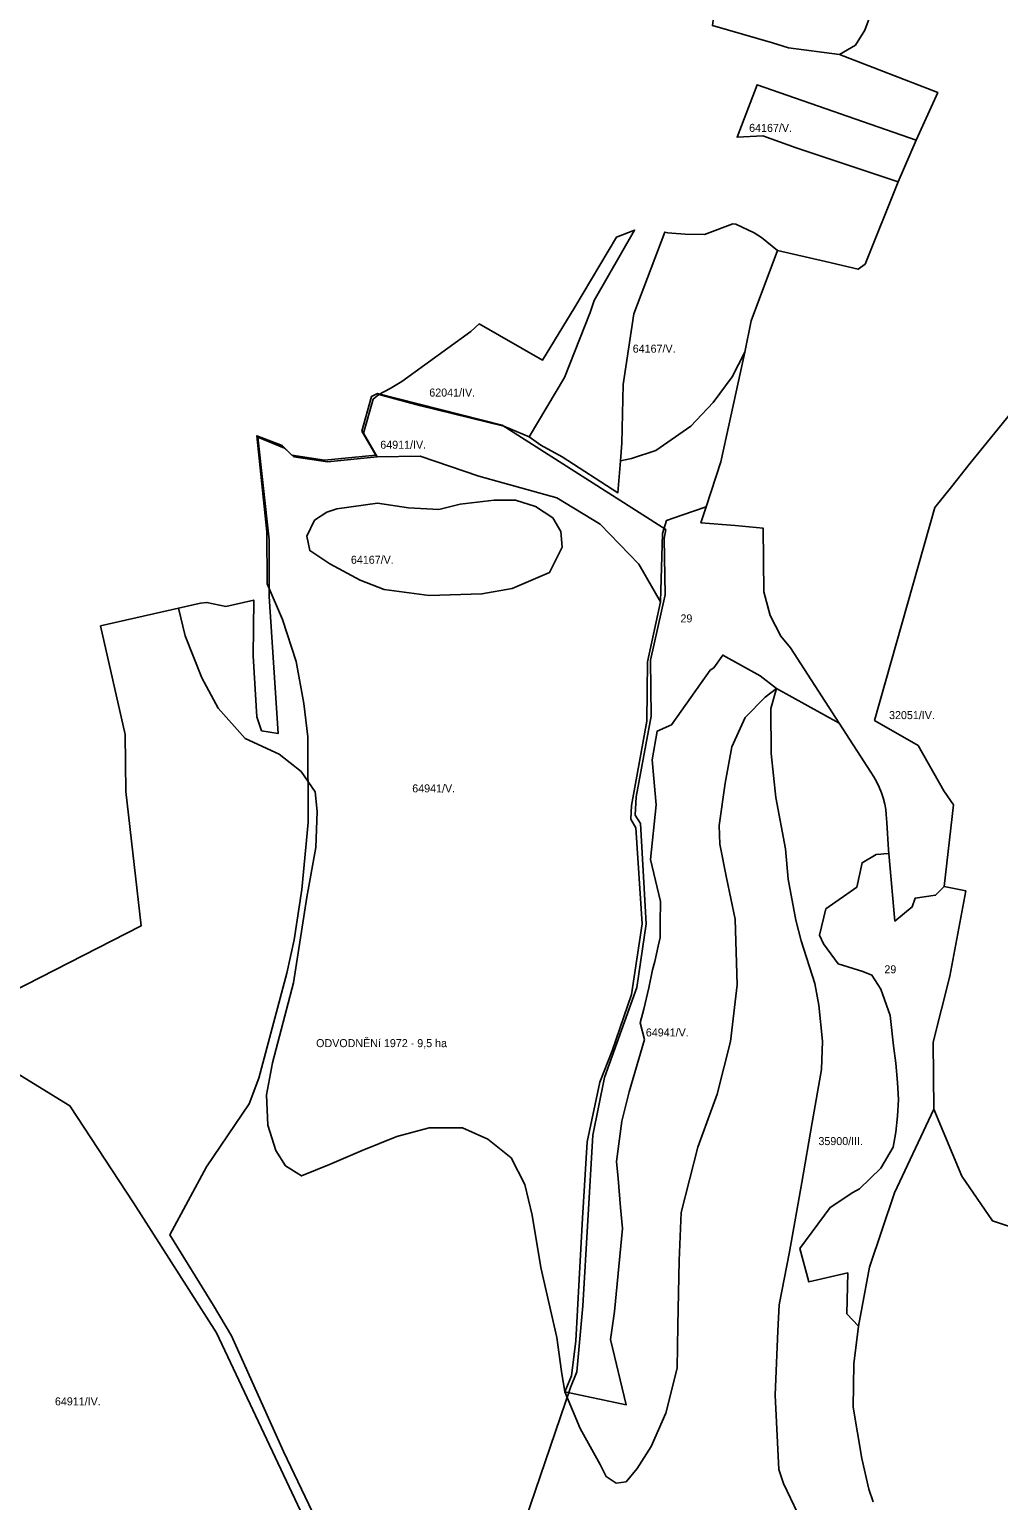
# Model space of a CAD drawing. Extents: x -521621 to -516761, y -1190184 to -1184927.
# Drawn here: x -519274 to -518790, y -1186738 to -1186003 of the extents above; entities that cross this region are included whole.
import ezdxf

# ---------------------------------------------------------------- set-up
doc = ezdxf.new("R2010")
doc.units = 0
doc.layers.add('BPEJ_s', color=7, linetype='Continuous')
doc.layers.add('odvodneni_s', color=7, linetype='Continuous')

msp = doc.modelspace()

# ---------------------------------------------------------------- linework, layer by layer
at = {"layer": 'BPEJ_s'}
for points in [[(-518927.24, -1185953.94), (-518919.2, -1185957.47), (-518903.58, -1185964.54), (-518887.75, -1185971.74), (-518858.33, -1185984.63), (-518853.23, -1185985.04), (-518849.62, -1185983.57), (-518850.9, -1185988.03), (-518856.42, -1186002.95), (-518861.03, -1186010.39), (-518869.09, -1186015.13), (-518894.47, -1186011.75), (-518902.58, -1186009.28), (-518932.52, -1186000.68), (-518929.68, -1185977.74), (-518926.98, -1185957.49)], [(-518839.76, -1186078.8), (-518890.62, -1186061.79), (-518907.36, -1186055.72), (-518920.21, -1186056.45), (-518910.27, -1186030.23), (-518830.77, -1186057.92)], [(-518978.56, -1186218.19), (-518977.87, -1186209.43), (-518977.14, -1186180.08), (-518971.74, -1186144.66), (-518956.26, -1186103.89), (-518954.89, -1186104.16), (-518952.82, -1186104.31), (-518946.24, -1186104.81), (-518936.52, -1186105.07), (-518922.31, -1186099.75), (-518920.92, -1186099.86), (-518911.74, -1186104.17), (-518907.96, -1186106.55), (-518900, -1186113.07), (-518913.14, -1186148.14), (-518916.35, -1186163.9), (-518922.7, -1186176.15), (-518932.15, -1186189.09), (-518943.34, -1186200.87), (-518960.9, -1186213.03), (-518973.06, -1186217.09)], [(-519099.23, -1186185.06), (-519093.67, -1186182.05), (-519087.79, -1186178.57), (-519053.23, -1186153.53), (-519049.1, -1186149.76), (-519017.53, -1186167.93), (-519001.26, -1186141.37), (-518980.5, -1186106.34), (-518971.45, -1186102.82), (-518991.71, -1186138.02), (-518993.72, -1186144.06), (-519006.47, -1186176.56), (-519024.12, -1186206.22), (-519036.73, -1186200.92), (-519078.87, -1186190.51)], [(-519100.11, -1186216.23), (-519106.93, -1186204.32), (-519102.12, -1186187.28), (-519099.23, -1186185.06), (-519078.87, -1186190.51), (-519036.73, -1186200.92), (-519024.12, -1186206.22), (-519018.33, -1186210.38), (-519007.58, -1186216.1), (-518979.81, -1186234.14), (-518978.56, -1186218.19), (-518973.06, -1186217.09), (-518960.9, -1186213.03), (-518943.34, -1186200.87), (-518932.15, -1186189.09), (-518922.7, -1186176.15), (-518916.35, -1186163.9), (-518924.26, -1186199.68), (-518928.29, -1186218.68), (-518935.71, -1186241.21), (-518947.84, -1186245.34), (-518955.44, -1186247.99), (-518957.48, -1186254.45), (-518958.55, -1186288.61), (-518969.39, -1186269.9), (-518988.69, -1186249.81), (-519010.3, -1186236.69), (-519049.28, -1186225.87), (-519078.61, -1186215.83)], [(-519199.32, -1186291.85), (-519188.43, -1186289.39), (-519185.21, -1186288.91), (-519175.79, -1186290.98), (-519161.77, -1186287.76), (-519162, -1186315.6), (-519160.16, -1186346.2), (-519157.86, -1186353.1), (-519149.59, -1186354.48), (-519154.05, -1186286.04), (-519154.05, -1186257.68), (-519159.74, -1186206.3), (-519146.35, -1186211.89), (-519141.76, -1186216.11), (-519124.9, -1186218.71), (-519100.11, -1186216.23), (-519078.61, -1186215.83), (-519049.28, -1186225.87), (-519010.3, -1186236.69), (-518988.69, -1186249.81), (-518969.39, -1186269.9), (-518958.55, -1186288.61), (-518964.97, -1186318.69), (-518965.37, -1186348.37), (-518972.98, -1186390.49), (-518973.26, -1186397.21), (-518970.84, -1186401.56), (-518967.71, -1186449.61), (-518973.02, -1186484.86), (-518982.62, -1186513.12), (-518988.81, -1186528.68), (-518995.15, -1186558.48), (-518997.41, -1186596.66), (-519000.81, -1186658.07), (-519003.05, -1186675.54), (-519006.29, -1186683.46), (-519007.95, -1186673.29), (-519010.28, -1186656.33), (-519018.25, -1186621.43), (-519022.57, -1186595.17), (-519026.22, -1186579.87), (-519033.2, -1186566.58), (-519044.83, -1186557.27), (-519057.45, -1186551.62), (-519074.06, -1186551.62), (-519090.34, -1186555.94), (-519107.62, -1186562.92), (-519123.9, -1186569.9), (-519137.85, -1186575.55), (-519145.83, -1186570.56), (-519150.81, -1186562.92), (-519154.8, -1186550.29), (-519155.46, -1186535), (-519152.47, -1186519.04), (-519141.84, -1186479.15), (-519135.19, -1186436.26), (-519130.72, -1186411.48), (-519130.11, -1186393.52), (-519131.03, -1186383.61), (-519138.15, -1186373.39), (-519148.98, -1186364.72), (-519166.01, -1186356.97), (-519179.62, -1186341.8), (-519187.67, -1186326.62), (-519196.03, -1186305.57)], [(-519030.98, -1186237.83), (-519020.92, -1186241.04), (-519012.32, -1186246.73), (-519008.38, -1186253.44), (-519007.66, -1186261.32), (-519013.93, -1186274.01), (-519032.59, -1186282.04), (-519047.75, -1186284.66), (-519074.14, -1186285.54), (-519096.6, -1186282.47), (-519108.56, -1186277.8), (-519123.72, -1186269.63), (-519133.78, -1186263.07), (-519135.24, -1186255.77), (-519131.45, -1186247.9), (-519125.32, -1186243.81), (-519120.3, -1186242.09), (-519099.84, -1186239.39), (-519084.4, -1186241.71), (-519069.35, -1186242.48), (-519058.55, -1186239.77), (-519041.56, -1186237.84)], [(-519030.98, -1186237.83), (-519020.92, -1186241.04), (-519012.32, -1186246.73), (-519008.38, -1186253.44), (-519007.66, -1186261.32), (-519013.93, -1186274.01), (-519032.59, -1186282.04), (-519047.75, -1186284.66), (-519074.14, -1186285.54), (-519096.6, -1186282.47), (-519108.56, -1186277.8), (-519123.72, -1186269.63), (-519133.78, -1186263.07), (-519135.24, -1186255.77), (-519131.45, -1186247.9), (-519125.32, -1186243.81), (-519120.3, -1186242.09), (-519099.84, -1186239.39), (-519084.4, -1186241.71), (-519069.35, -1186242.48), (-519058.55, -1186239.77), (-519041.56, -1186237.84)], [(-519006.29, -1186683.46), (-519003.05, -1186675.54), (-519000.81, -1186658.07), (-518997.41, -1186596.66), (-518995.15, -1186558.48), (-518988.81, -1186528.68), (-518982.62, -1186513.12), (-518973.02, -1186484.86), (-518967.71, -1186449.61), (-518970.84, -1186401.56), (-518973.26, -1186397.21), (-518972.98, -1186390.49), (-518965.37, -1186348.37), (-518964.97, -1186318.69), (-518958.55, -1186288.61), (-518957.48, -1186254.45), (-518955.44, -1186247.99), (-518947.84, -1186245.34), (-518935.71, -1186241.21), (-518938.33, -1186249.14), (-518921.14, -1186250.49), (-518907.24, -1186251.75), (-518906.8, -1186283.58), (-518903.75, -1186295.49), (-518898.38, -1186305.83), (-518893.45, -1186311.57), (-518869.16, -1186349.32), (-518900.51, -1186331.91), (-518908.64, -1186325.58), (-518927.41, -1186315.23), (-518931.81, -1186321.56), (-518933.69, -1186322.74), (-518953, -1186350.13), (-518960.15, -1186353.24), (-518962.63, -1186367.56), (-518960.61, -1186390.12), (-518963.46, -1186417.48), (-518958.46, -1186438.39), (-518958.72, -1186449.04), (-518958.59, -1186456.48), (-518959.62, -1186460.72), (-518961.41, -1186468.42), (-518962.57, -1186472.65), (-518964.36, -1186481.5), (-518966.76, -1186492.16), (-518968.74, -1186499.09), (-518966.56, -1186507.41), (-518974.08, -1186533.55), (-518977.84, -1186548.21), (-518980.41, -1186568.41), (-518979.62, -1186576.8), (-518978.46, -1186591.29), (-518977.49, -1186601.92), (-518981.55, -1186643.27), (-518983.43, -1186657.35), (-518975.63, -1186689.96)], [(-519006.29, -1186683.46), (-518975.63, -1186689.96), (-518983.43, -1186657.35), (-518981.55, -1186643.27), (-518977.49, -1186601.92), (-518978.46, -1186591.29), (-518979.62, -1186576.8), (-518980.41, -1186568.41), (-518977.84, -1186548.21), (-518974.08, -1186533.55), (-518966.56, -1186507.41), (-518968.74, -1186499.09), (-518966.76, -1186492.16), (-518964.36, -1186481.5), (-518962.57, -1186472.65), (-518961.41, -1186468.42), (-518959.62, -1186460.72), (-518958.59, -1186456.48), (-518958.72, -1186449.04), (-518958.46, -1186438.39), (-518963.46, -1186417.48), (-518960.61, -1186390.12), (-518962.63, -1186367.56), (-518960.15, -1186353.24), (-518953, -1186350.13), (-518933.69, -1186322.74), (-518931.81, -1186321.56), (-518927.41, -1186315.23), (-518908.64, -1186325.58), (-518900.51, -1186331.91), (-518906.18, -1186336.23), (-518916.25, -1186346.52), (-518922.89, -1186361.09), (-518926.1, -1186379.31), (-518929.1, -1186400.52), (-518928.86, -1186409.78), (-518925.56, -1186426.62), (-518921.24, -1186447.24), (-518920.24, -1186480.15), (-518923.56, -1186508.4), (-518930.21, -1186534.67), (-518939.84, -1186561.26), (-518948.15, -1186593.84), (-518949.15, -1186617.77), (-518949.81, -1186650.35), (-518950.14, -1186671.62), (-518955.79, -1186694.23), (-518963.1, -1186710.85), (-518970.08, -1186721.82), (-518975.72, -1186728.47), (-518980.71, -1186729.14), (-518985.69, -1186725.81), (-518988.68, -1186719.83), (-518998.65, -1186701.88)], [(-518859.55, -1186650.63), (-518865.37, -1186644.56), (-518864.88, -1186624.04), (-518884.37, -1186628.5), (-518888.84, -1186611.82), (-518873.77, -1186591.3), (-518862.41, -1186583.88), (-518858.99, -1186582.04), (-518848.36, -1186571.74), (-518842.15, -1186561.19), (-518840.85, -1186553.73), (-518840.02, -1186545.73), (-518839.63, -1186537.43), (-518840.09, -1186528.83), (-518840.93, -1186519.16), (-518842.07, -1186510.48), (-518843.67, -1186495.4), (-518848.46, -1186482.31), (-518852.84, -1186475.21), (-518857.37, -1186473.42), (-518869.66, -1186469.5), (-518877.07, -1186459.56), (-518879.12, -1186455.2), (-518875.79, -1186442.11), (-518860.41, -1186431.34), (-518857.75, -1186419.03), (-518850.72, -1186414.94), (-518848.43, -1186414.73), (-518846.9, -1186414.58), (-518844.45, -1186414.36), (-518841.34, -1186448.23), (-518832.8, -1186441.11), (-518831.24, -1186436.82), (-518821.02, -1186435.26), (-518816.66, -1186430.99), (-518805.93, -1186433.1), (-518813.91, -1186475.8), (-518822.21, -1186508.73), (-518821.82, -1186542.19), (-518841.54, -1186583.97), (-518854.04, -1186621.2)]]:
    msp.add_lwpolyline(points, close=True, dxfattribs=at)
for points in [[(-518779.14, -1186188.98), (-518803.71, -1186219.42), (-518813.03, -1186231.23), (-518821.34, -1186241.53), (-518851.51, -1186347.99), (-518829.78, -1186360.47), (-518816.88, -1186383.13), (-518812.11, -1186390.05), (-518816.66, -1186430.99), (-518821.02, -1186435.26), (-518831.24, -1186436.82), (-518832.8, -1186441.11), (-518841.34, -1186448.23), (-518844.45, -1186414.36), (-518844.61, -1186412.67), (-518845.46, -1186398.98), (-518845.71, -1186395), (-518845.93, -1186392.49), (-518846.44, -1186389.8), (-518847.28, -1186386.67), (-518848, -1186384.16), (-518849.29, -1186381.36), (-518850.52, -1186378.45), (-518851.91, -1186376.1), (-518853.37, -1186373.86), (-518869.16, -1186349.32), (-518893.45, -1186311.57), (-518898.38, -1186305.83), (-518903.75, -1186295.49), (-518906.8, -1186283.58), (-518907.24, -1186251.75), (-518921.14, -1186250.49), (-518938.33, -1186249.14), (-518935.71, -1186241.21), (-518928.29, -1186218.68), (-518924.26, -1186199.68), (-518916.35, -1186163.9), (-518913.14, -1186148.14), (-518900, -1186113.07), (-518876.03, -1186118.57), (-518859.72, -1186122.44), (-518856.24, -1186119.82), (-518839.76, -1186078.8), (-518830.77, -1186057.92), (-518819.98, -1186034.16), (-518869.09, -1186015.13), (-518861.03, -1186010.39), (-518856.42, -1186002.95), (-518850.9, -1185988.03)], [(-518932.52, -1186000.68), (-518902.58, -1186009.28), (-518894.47, -1186011.75), (-518869.09, -1186015.13), (-518819.98, -1186034.16), (-518830.77, -1186057.92), (-518910.27, -1186030.23), (-518920.21, -1186056.45), (-518907.36, -1186055.72), (-518890.62, -1186061.79), (-518839.76, -1186078.8), (-518856.24, -1186119.82), (-518859.72, -1186122.44), (-518876.03, -1186118.57), (-518900, -1186113.07), (-518907.96, -1186106.55), (-518911.74, -1186104.17), (-518920.92, -1186099.86), (-518922.31, -1186099.75), (-518936.52, -1186105.07), (-518946.24, -1186104.81), (-518952.82, -1186104.31), (-518954.89, -1186104.16), (-518956.26, -1186103.89), (-518971.74, -1186144.66), (-518977.14, -1186180.08), (-518977.87, -1186209.43), (-518978.56, -1186218.19), (-518979.81, -1186234.14), (-519007.58, -1186216.1), (-519018.33, -1186210.38), (-519024.12, -1186206.22), (-519006.47, -1186176.56), (-518993.72, -1186144.06), (-518991.71, -1186138.02), (-518971.45, -1186102.82), (-518980.5, -1186106.34), (-519001.26, -1186141.37), (-519017.53, -1186167.93), (-519049.1, -1186149.76), (-519053.23, -1186153.53), (-519087.79, -1186178.57), (-519093.67, -1186182.05), (-519099.23, -1186185.06), (-519102.12, -1186187.28), (-519106.93, -1186204.32), (-519100.11, -1186216.23), (-519124.9, -1186218.71), (-519141.76, -1186216.11), (-519146.35, -1186211.89), (-519159.74, -1186206.3), (-519154.05, -1186257.68), (-519154.05, -1186286.04), (-519149.59, -1186354.48), (-519157.86, -1186353.1), (-519160.16, -1186346.2), (-519162, -1186315.6), (-519161.77, -1186287.76), (-519175.79, -1186290.98), (-519185.21, -1186288.91), (-519188.43, -1186289.39), (-519199.32, -1186291.85), (-519238.33, -1186300.66), (-519226.01, -1186354.88), (-519225.76, -1186383.49), (-519218.04, -1186450.6), (-519297.4, -1186491.12)], [(-518778, -1186602.88), (-518792.61, -1186598), (-518807.83, -1186575.77), (-518821.82, -1186542.19), (-518822.21, -1186508.73), (-518813.91, -1186475.8), (-518805.93, -1186433.1), (-518816.66, -1186430.99), (-518812.11, -1186390.05), (-518816.88, -1186383.13), (-518829.78, -1186360.47), (-518851.51, -1186347.99), (-518821.34, -1186241.53), (-518813.03, -1186231.23), (-518803.71, -1186219.42), (-518779.14, -1186188.98)], [(-519297.4, -1186491.12), (-519218.04, -1186450.6), (-519225.76, -1186383.49), (-519226.01, -1186354.88), (-519238.33, -1186300.66), (-519199.32, -1186291.85), (-519196.03, -1186305.57), (-519187.67, -1186326.62), (-519179.62, -1186341.8), (-519166.01, -1186356.97), (-519148.98, -1186364.72), (-519138.15, -1186373.39), (-519131.03, -1186383.61), (-519130.11, -1186393.52), (-519130.72, -1186411.48), (-519135.19, -1186436.26), (-519141.84, -1186479.15), (-519152.47, -1186519.04), (-519155.46, -1186535), (-519154.8, -1186550.29), (-519150.81, -1186562.92), (-519145.83, -1186570.56), (-519137.85, -1186575.55), (-519123.9, -1186569.9), (-519107.62, -1186562.92), (-519090.34, -1186555.94), (-519074.06, -1186551.62), (-519057.45, -1186551.62), (-519044.83, -1186557.27), (-519033.2, -1186566.58), (-519026.22, -1186579.87), (-519022.57, -1186595.17), (-519018.25, -1186621.43), (-519010.28, -1186656.33), (-519007.95, -1186673.29), (-519006.29, -1186683.46), (-518998.65, -1186701.88), (-518988.68, -1186719.83), (-518985.69, -1186725.81), (-518980.71, -1186729.14), (-518975.72, -1186728.47), (-518970.08, -1186721.82), (-518963.1, -1186710.85), (-518955.79, -1186694.23), (-518950.14, -1186671.62), (-518949.81, -1186650.35), (-518949.15, -1186617.77), (-518948.15, -1186593.84), (-518939.84, -1186561.26), (-518930.21, -1186534.67), (-518923.56, -1186508.4), (-518920.24, -1186480.15), (-518921.24, -1186447.24), (-518925.56, -1186426.62), (-518928.86, -1186409.78), (-518929.1, -1186400.52), (-518926.1, -1186379.31), (-518922.89, -1186361.09), (-518916.25, -1186346.52), (-518906.18, -1186336.23), (-518900.51, -1186331.91), (-518903.4, -1186342.02), (-518903.19, -1186364.52), (-518900.83, -1186386.38), (-518896.11, -1186412.13), (-518894.69, -1186427.31), (-518890.85, -1186447.75), (-518888.22, -1186458.07), (-518881.34, -1186479.33), (-518879.32, -1186490.26), (-518877.5, -1186508.27), (-518878.11, -1186522.44), (-518882.66, -1186548.86), (-518887.92, -1186578.81), (-518893.97, -1186613.54), (-518899.14, -1186640.03), (-518899.89, -1186653.03), (-518901.18, -1186685.21), (-518899.4, -1186722.39), (-518897.01, -1186729.33), (-518886.54, -1186751.27)], [(-518886.54, -1186751.27), (-518897.01, -1186729.33), (-518899.4, -1186722.39), (-518901.18, -1186685.21), (-518899.89, -1186653.03), (-518899.14, -1186640.03), (-518893.97, -1186613.54), (-518887.92, -1186578.81), (-518882.66, -1186548.86), (-518878.11, -1186522.44), (-518877.5, -1186508.27), (-518879.32, -1186490.26), (-518881.34, -1186479.33), (-518888.22, -1186458.07), (-518890.85, -1186447.75), (-518894.69, -1186427.31), (-518896.11, -1186412.13), (-518900.83, -1186386.38), (-518903.19, -1186364.52), (-518903.4, -1186342.02), (-518900.51, -1186331.91), (-518869.16, -1186349.32), (-518853.37, -1186373.86), (-518851.91, -1186376.1), (-518850.52, -1186378.45), (-518849.29, -1186381.36), (-518848, -1186384.16), (-518847.28, -1186386.67), (-518846.44, -1186389.8), (-518845.93, -1186392.49), (-518845.71, -1186395), (-518845.46, -1186398.98), (-518844.61, -1186412.67), (-518844.45, -1186414.36), (-518846.9, -1186414.58), (-518848.43, -1186414.73), (-518850.72, -1186414.94), (-518857.75, -1186419.03), (-518860.41, -1186431.34), (-518875.79, -1186442.11), (-518879.12, -1186455.2), (-518877.07, -1186459.56), (-518869.66, -1186469.5), (-518857.37, -1186473.42), (-518852.84, -1186475.21), (-518848.46, -1186482.31), (-518843.67, -1186495.4), (-518842.07, -1186510.48), (-518840.93, -1186519.16), (-518840.09, -1186528.83), (-518839.63, -1186537.43), (-518840.02, -1186545.73), (-518840.85, -1186553.73), (-518842.15, -1186561.19), (-518848.36, -1186571.74), (-518858.99, -1186582.04), (-518862.41, -1186583.88), (-518873.77, -1186591.3), (-518888.84, -1186611.82), (-518884.37, -1186628.5), (-518864.88, -1186624.04), (-518865.37, -1186644.56), (-518859.55, -1186650.63), (-518861.94, -1186669.42), (-518862.19, -1186691.23), (-518857.93, -1186716.79), (-518854.42, -1186732.09), (-518852.18, -1186738.42)], [(-518852.18, -1186738.42), (-518854.42, -1186732.09), (-518857.93, -1186716.79), (-518862.19, -1186691.23), (-518861.94, -1186669.42), (-518859.55, -1186650.63), (-518854.04, -1186621.2), (-518841.54, -1186583.97), (-518821.82, -1186542.19), (-518807.83, -1186575.77), (-518792.61, -1186598), (-518778, -1186602.88)]]:
    msp.add_lwpolyline(points, dxfattribs=at)
at = {"layer": 'odvodneni_s'}
for points in [[(-519110.84, -1186788.68), (-519146.97, -1186713.39), (-519172.87, -1186655.43), (-519181.8, -1186640.27), (-519203.78, -1186604.96), (-519185.38, -1186571.06), (-519164.11, -1186539.61), (-519159.22, -1186526.76), (-519145.26, -1186474.27), (-519141.63, -1186457.51), (-519137.72, -1186432.38), (-519134.65, -1186398.87), (-519134.79, -1186356.15), (-519136.74, -1186339.39), (-519140.65, -1186318.45), (-519147.35, -1186297.51), (-519155.12, -1186279.58), (-519155.23, -1186253.66), (-519160.22, -1186205.67), (-519147.55, -1186210.53), (-519142.68, -1186215.27), (-519126.43, -1186217.83), (-519100.71, -1186215.27), (-519107.75, -1186203.36), (-519102.88, -1186185.96), (-519099.94, -1186184.55), (-519037.61, -1186200.42), (-518955.84, -1186252.51), (-518956.7, -1186257.06), (-518956.16, -1186285.13), (-518963.41, -1186317.85), (-518963.14, -1186345.78), (-518970.67, -1186386.18), (-518971.22, -1186395.35), (-518968.48, -1186399.46), (-518965.6, -1186449.57), (-518970.4, -1186481.48), (-518986.42, -1186526.39), (-518992.3, -1186555.14), (-518997.37, -1186640.58), (-519000.38, -1186673.45), (-519003.53, -1186681.39), (-519051.29, -1186821.65)], [(-519282.73, -1186522.69), (-519253.62, -1186540.63), (-519221.82, -1186589.06), (-519180.32, -1186653.96), (-519107.8, -1186808)]]:
    msp.add_lwpolyline(points, dxfattribs=at)

# ---------------------------------------------------------------- texts
at = {"layer": 'BPEJ_s'}
for s, p in [('64167/V.', (-518914.2, -1186053.77)), ('64167/V.', (-518972.38, -1186164.12)), ('62041/IV.', (-519074.03, -1186186.05)), ('64911/IV.', (-519098.53, -1186212.13)), ('64167/V.', (-519113.21, -1186269.63)), ('29', (-518948.52, -1186298.94)), ('32051/IV.', (-518844.28, -1186347.27)), ('64941/V.', (-519082.55, -1186383.89)), ('29', (-518846.61, -1186474.31)), ('64941/V.', (-518965.81, -1186505.87)), ('35900/III.', (-518879.57, -1186560.18)), ('64911/IV.', (-519261.12, -1186690.26))]:
    msp.add_text(s, height=4, dxfattribs=at).set_placement(p)
at = {"layer": 'odvodneni_s'}
msp.add_text('ODVODNĚNí 1972 - 9,5 ha', height=4, dxfattribs=at).set_placement((-519130.6, -1186511.21))

doc.saveas('drawing.dxf')
